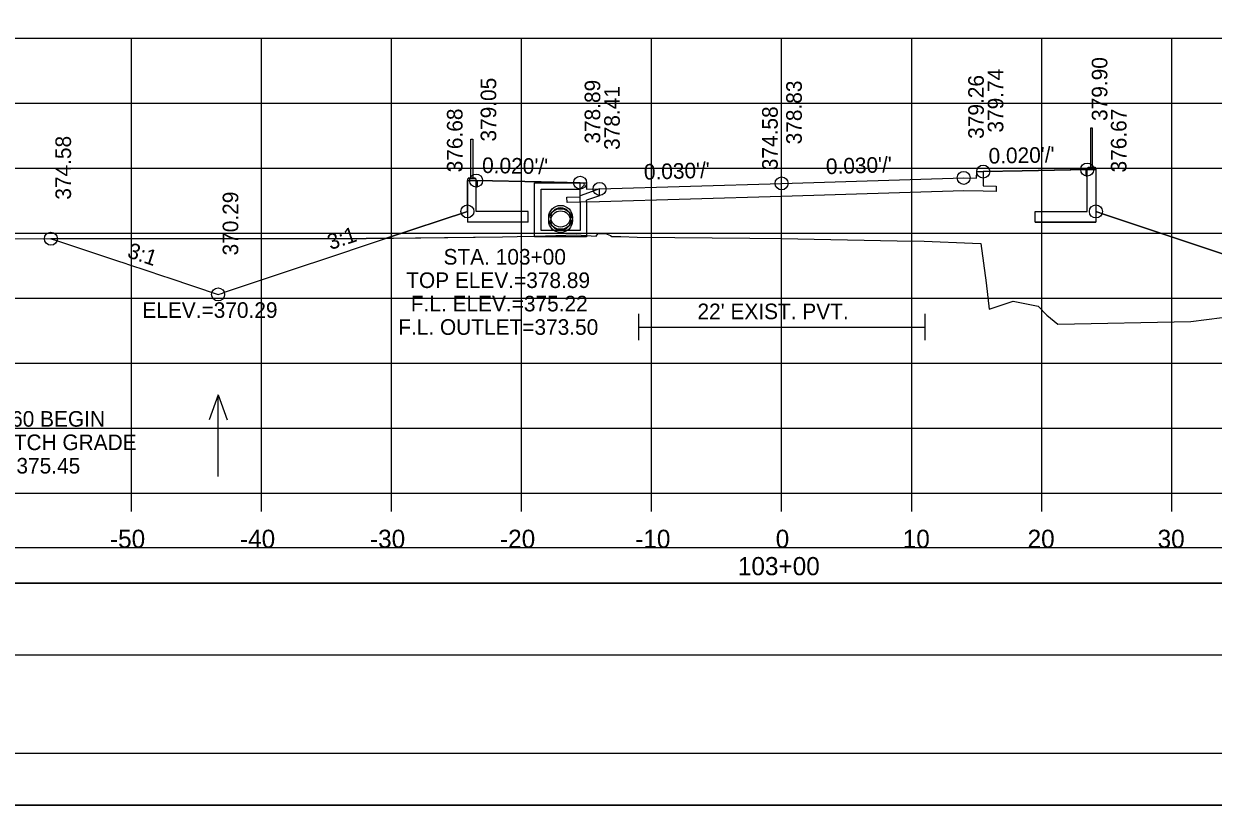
# Model space of a CAD drawing. Extents: x -37291014 to -37290680, y -936053 to -933067.
# Drawn here: x -37290901.4 to -37290809.9, y -935413.3 to -935353.2 of the extents above; entities that cross this region are included whole.
import ezdxf

# ---------------------------------------------------------------- set-up
doc = ezdxf.new("R2010")
doc.units = 0
for name, color, linetype in [('Default', 7, 'Continuous'), ('R_Alt Surface', 7, 'Continuous'), ('R_Axis', 7, 'Continuous'), ('R_Axis Annot', 7, 'Continuous'), ('R_Border', 7, 'Continuous'), ('R_Contours', 7, 'Continuous'), ('R_Exist Surface', 7, 'Continuous'), ('R_Fin Surface', 7, 'Continuous'), ('R_Grid', 7, 'Continuous'), ('R_No Plot', 7, 'Continuous'), ('R_Water', 7, 'Continuous'), ('R_Water Annot', 7, 'Continuous'), ('R_Xsect Elev', 7, 'Continuous'), ('R_Xsect Slope', 7, 'Continuous')]:
    doc.layers.add(name, color=color, linetype=linetype)

msp = doc.modelspace()

# ---------------------------------------------------------------- linework, layer by layer
at = {"layer": 'Default'}
for p, q in [((-37290819.352, -935361.226), (-37290819.352, -935364.226)), ((-37290819.185, -935361.226), (-37290819.352, -935361.226)), ((-37290819.185, -935364.226), (-37290819.185, -935361.226)), ((-37290867.018, -935365.076), (-37290867.018, -935362.076)), ((-37290867.018, -935362.076), (-37290866.852, -935362.076)), ((-37290866.852, -935362.076), (-37290866.852, -935365.076)), ((-37290819.602, -935364.309), (-37290819.539, -935364.246)), ((-37290819.602, -935367.64), (-37290819.602, -935364.309)), ((-37290819.539, -935364.226), (-37290818.997, -935364.226)), ((-37290819.539, -935364.246), (-37290819.539, -935364.226)), ((-37290819.539, -935364.246), (-37290818.997, -935364.246)), ((-37290818.997, -935364.226), (-37290818.997, -935364.246)), ((-37290818.997, -935364.246), (-37290818.935, -935364.309)), ((-37290818.935, -935364.309), (-37290818.935, -935368.473)), ((-37290867.206, -935365.097), (-37290867.268, -935365.16)), ((-37290867.268, -935365.16), (-37290867.268, -935368.463)), ((-37290866.664, -935365.076), (-37290867.206, -935365.076)), ((-37290867.206, -935365.076), (-37290867.206, -935365.097)), ((-37290866.664, -935365.097), (-37290867.206, -935365.097)), ((-37290866.664, -935365.097), (-37290866.664, -935365.076)), ((-37290866.602, -935365.16), (-37290866.664, -935365.097)), ((-37290866.602, -935367.63), (-37290866.602, -935365.16)), ((-37290862.598, -935367.63), (-37290866.602, -935367.63)), ((-37290862.598, -935368.463), (-37290862.598, -935367.63)), ((-37290823.605, -935368.473), (-37290823.605, -935367.64)), ((-37290823.605, -935367.64), (-37290819.602, -935367.64)), ((-37290862.598, -935368.463), (-37290867.268, -935368.463)), ((-37290823.605, -935368.473), (-37290818.935, -935368.473))]:
    msp.add_line(p, q, dxfattribs=at)
for points in [[(-37290819.685, -935364.913), (-37290819.602, -935364.913), (-37290819.602, -935364.413), (-37290819.685, -935364.413), (-37290819.685, -935364.913)], [(-37290866.518, -935365.764), (-37290866.602, -935365.764), (-37290866.602, -935365.264), (-37290866.518, -935365.264), (-37290866.518, -935365.764)]]:
    msp.add_lwpolyline(points, dxfattribs=at)
for points in [[(-37290992.481, -935396.216), (-37290693.722, -935396.216), (-37290693.722, -935393.51), (-37290992.481, -935393.51)], [(-37290992.481, -935401.738), (-37290693.722, -935401.738), (-37290693.722, -935396.216), (-37290992.481, -935396.216)]]:
    msp.add_lwpolyline(points, close=True, dxfattribs=at)
at = {"layer": 'R_Alt Surface'}
for points in [[(-37290827.602, -935364.573), (-37290827.602, -935365.666), (-37290826.592, -935365.686), (-37290826.602, -935366.103), (-37290827.602, -935366.083), (-37290829.102, -935366.053), (-37290843.102, -935366.478), (-37290857.102, -935366.904), (-37290858.602, -935366.934), (-37290859.602, -935366.954), (-37290859.612, -935366.537), (-37290858.602, -935366.517), (-37290858.602, -935365.424)], [(-37290854.102, -935375.522), (-37290854.102, -935377.522)], [(-37290832.102, -935375.522), (-37290832.102, -935377.522)], [(-37290854.102, -935376.522), (-37290832.102, -935376.522)]]:
    msp.add_lwpolyline(points, dxfattribs=at)
at = {"layer": 'R_Axis'}
for p, q in [((-37290993.102, -935389.31), (-37290693.102, -935389.31)), ((-37290893.102, -935390.71), (-37290893.102, -935389.31)), ((-37290883.102, -935390.71), (-37290883.102, -935389.31)), ((-37290873.102, -935390.71), (-37290873.102, -935389.31)), ((-37290863.102, -935390.71), (-37290863.102, -935389.31)), ((-37290853.102, -935390.71), (-37290853.102, -935389.31)), ((-37290843.102, -935390.71), (-37290843.102, -935389.31)), ((-37290833.102, -935390.71), (-37290833.102, -935389.31)), ((-37290823.102, -935390.71), (-37290823.102, -935389.31)), ((-37290813.102, -935390.71), (-37290813.102, -935389.31))]:
    msp.add_line(p, q, dxfattribs=at)
at = {"layer": 'R_Border'}
msp.add_line((-37290684.921, -935409.31), (-37291001.102, -935409.31), dxfattribs=at)
at = {"layer": 'R_Contours'}
for p, q in [((-37290819.602, -935367.64), (-37290819.602, -935364.913)), ((-37290823.605, -935368.473), (-37290823.605, -935367.64)), ((-37290823.605, -935367.64), (-37290819.602, -935367.64)), ((-37290818.935, -935367.64), (-37290818.935, -935368.473)), ((-37290818.935, -935368.473), (-37290823.605, -935368.473)), ((-37290875.057, -935369.719), (-37290899.307, -935369.733)), ((-37290873.484, -935369.7), (-37290875.057, -935369.719))]:
    msp.add_line(p, q, dxfattribs=at)
for points in [[(-37290819.685, -935364.415), (-37290824.602, -935364.513), (-37290827.602, -935364.573)], [(-37290819.602, -935364.913), (-37290819.685, -935364.913), (-37290819.685, -935364.415)], [(-37290858.602, -935365.424), (-37290861.602, -935365.364), (-37290866.602, -935365.264), (-37290867.272, -935365.264), (-37290867.273, -935367.63), (-37290873.484, -935369.7)], [(-37290827.602, -935364.573), (-37290827.602, -935365.666), (-37290826.592, -935365.686), (-37290826.602, -935366.103), (-37290827.602, -935366.083), (-37290829.102, -935366.053), (-37290843.102, -935366.478), (-37290857.102, -935366.904), (-37290858.602, -935366.934), (-37290859.602, -935366.954), (-37290859.612, -935366.537), (-37290858.602, -935366.517), (-37290858.602, -935365.424)], [(-37290818.931, -935367.64), (-37290818.935, -935367.64)], [(-37290796.525, -935375.107), (-37290798.192, -935374.566), (-37290798.385, -935374.504), (-37290818.199, -935367.884), (-37290818.931, -935367.64)], [(-37290899.307, -935369.733), (-37290899.032, -935369.823), (-37290894.19, -935371.43), (-37290893.608, -935371.621), (-37290893.34, -935371.711), (-37290891.917, -935372.183), (-37290890.728, -935372.583), (-37290890.247, -935372.746), (-37290886.444, -935374.02), (-37290886.119, -935373.911), (-37290885.943, -935373.853), (-37290879.345, -935371.649), (-37290879.077, -935371.559), (-37290873.484, -935369.7)], [(-37290873.484, -935369.7), (-37290864.579, -935369.594), (-37290863.438, -935369.567), (-37290862.072, -935369.536), (-37290858.894, -935369.432), (-37290857.375, -935369.542), (-37290857.24, -935369.359), (-37290856.642, -935369.332), (-37290856.266, -935369.487), (-37290856.162, -935369.56), (-37290855.462, -935369.571), (-37290854.208, -935369.605), (-37290845.556, -935369.695), (-37290843.14, -935369.726), (-37290834.226, -935369.884), (-37290832.13, -935369.923), (-37290828.416, -935370.082), (-37290827.782, -935370.106), (-37290827.37, -935373.135), (-37290827.148, -935375.144), (-37290825.302, -935374.524), (-37290823.371, -935374.908), (-37290822.714, -935375.622), (-37290821.871, -935376.316), (-37290811.629, -935376.105), (-37290809.219, -935375.784)]]:
    msp.add_lwpolyline(points, dxfattribs=at)
at = {"layer": 'R_Exist Surface'}
msp.add_lwpolyline([(-37290913.949, -935369.741), (-37290875.057, -935369.719), (-37290864.579, -935369.594), (-37290863.438, -935369.567), (-37290862.072, -935369.536), (-37290858.894, -935369.432), (-37290857.375, -935369.542), (-37290857.24, -935369.359), (-37290856.642, -935369.332), (-37290856.266, -935369.487), (-37290856.162, -935369.56), (-37290855.462, -935369.571), (-37290854.208, -935369.605), (-37290845.556, -935369.695), (-37290843.14, -935369.726), (-37290834.226, -935369.884), (-37290832.13, -935369.923), (-37290828.416, -935370.082), (-37290827.782, -935370.106), (-37290827.37, -935373.135), (-37290827.148, -935375.144), (-37290825.302, -935374.524), (-37290823.371, -935374.908), (-37290822.714, -935375.622), (-37290821.871, -935376.316), (-37290811.629, -935376.105), (-37290809.219, -935375.784)], dxfattribs=at)
at = {"layer": 'R_Fin Surface'}
msp.add_lwpolyline([(-37290899.307, -935369.733), (-37290899.032, -935369.823), (-37290894.19, -935371.43), (-37290893.608, -935371.621), (-37290893.34, -935371.711), (-37290891.917, -935372.183), (-37290890.728, -935372.583), (-37290890.247, -935372.746), (-37290886.444, -935374.02), (-37290886.119, -935373.911), (-37290885.943, -935373.853), (-37290879.345, -935371.649), (-37290879.077, -935371.559), (-37290873.484, -935369.7), (-37290867.273, -935367.63), (-37290867.272, -935365.264), (-37290866.602, -935365.264), (-37290861.602, -935365.364), (-37290858.602, -935365.424), (-37290858.102, -935365.424), (-37290858.101, -935365.924), (-37290857.102, -935365.904), (-37290843.102, -935365.478), (-37290829.102, -935365.053), (-37290828.103, -935365.073), (-37290828.102, -935364.573), (-37290827.602, -935364.573), (-37290824.602, -935364.513), (-37290819.602, -935364.413), (-37290818.932, -935364.413), (-37290818.931, -935367.64), (-37290818.199, -935367.884), (-37290798.385, -935374.504)], dxfattribs=at)
at = {"layer": 'R_Grid'}
for p, q in [((-37290993.102, -935354.31), (-37290693.102, -935354.31)), ((-37290893.102, -935389.31), (-37290893.102, -935354.31)), ((-37290883.102, -935389.31), (-37290883.102, -935354.31)), ((-37290873.102, -935389.31), (-37290873.102, -935354.31)), ((-37290863.102, -935389.31), (-37290863.102, -935354.31)), ((-37290853.102, -935389.31), (-37290853.102, -935354.31)), ((-37290843.102, -935389.31), (-37290843.102, -935354.31)), ((-37290833.102, -935389.31), (-37290833.102, -935354.31)), ((-37290823.102, -935389.31), (-37290823.102, -935354.31)), ((-37290813.102, -935389.31), (-37290813.102, -935354.31)), ((-37290993.102, -935359.31), (-37290693.102, -935359.31)), ((-37290993.102, -935364.31), (-37290693.102, -935364.31)), ((-37290993.102, -935369.31), (-37290693.102, -935369.31)), ((-37290993.102, -935374.31), (-37290693.102, -935374.31)), ((-37290993.102, -935379.31), (-37290693.102, -935379.31)), ((-37290993.102, -935384.31), (-37290693.102, -935384.31)), ((-37290993.102, -935389.31), (-37290693.102, -935389.31))]:
    msp.add_line(p, q, dxfattribs=at)
at = {"layer": 'R_No Plot'}
msp.add_line((-37291013.502, -935413.288), (-37290680.169, -935413.288), dxfattribs=at)
for points in [[(-37291013.509, -935199.955), (-37290680.169, -935199.955), (-37290680.169, -935413.293), (-37291013.509, -935413.293)], [(-37290767.182, -935203.85), (-37290747.562, -935203.85), (-37290747.562, -935213.73), (-37290731.449, -935213.73), (-37290708.25, -935213.73), (-37290708.25, -935238.062), (-37290684.921, -935238.062), (-37290684.921, -935409.31), (-37291001.102, -935409.31), (-37291001.102, -935203.85)]]:
    msp.add_lwpolyline(points, close=True, dxfattribs=at)
for centre, radius in [((-37290827.602, -935364.573), 0.5), ((-37290819.602, -935364.413), 0.5), ((-37290866.602, -935365.264), 0.5), ((-37290858.602, -935365.424), 0.5), ((-37290857.102, -935365.904), 0.5), ((-37290843.102, -935365.478), 0.5), ((-37290829.102, -935365.053), 0.5), ((-37290829.102, -935365.053), 0.5), ((-37290867.273, -935367.63), 0.5), ((-37290860.102, -935368.09), 0.917), ((-37290818.931, -935367.64), 0.5), ((-37290860.102, -935368.34), 0.917), ((-37290899.307, -935369.733), 0.5), ((-37290886.444, -935374.02), 0.5)]:
    msp.add_circle(centre, radius, dxfattribs=at)
at = {"layer": 'R_Water'}
for p, q in [((-37290862.102, -935365.424), (-37290858.352, -935365.424)), ((-37290861.602, -935365.924), (-37290858.602, -935365.924)), ((-37290858.269, -935365.589), (-37290858.602, -935365.924)), ((-37290857.102, -935365.904), (-37290858.602, -935366.424)), ((-37290858.269, -935365.589), (-37290858.352, -935365.424)), ((-37290858.602, -935366.924), (-37290858.602, -935366.424)), ((-37290857.102, -935366.433), (-37290858.102, -935366.78)), ((-37290858.102, -935366.924), (-37290858.102, -935366.78))]:
    msp.add_line(p, q, dxfattribs=at)
for points in [[(-37290858.102, -935366.924), (-37290858.102, -935369.59), (-37290860.102, -935369.59), (-37290862.102, -935369.59), (-37290862.102, -935365.424)], [(-37290858.602, -935366.924), (-37290858.602, -935369.09), (-37290860.102, -935369.09), (-37290861.602, -935369.09), (-37290861.602, -935365.924)], [(-37290857.102, -935366.433), (-37290857.102, -935365.904)]]:
    msp.add_lwpolyline(points, dxfattribs=at)
for centre in [(-37290860.102, -935368.09), (-37290860.102, -935368.34)]:
    msp.add_circle(centre, 0.75, dxfattribs=at)
at = {"layer": 'R_Water Annot'}
for p, q in [((-37290886.444, -935381.741), (-37290887.144, -935383.664)), ((-37290886.444, -935388.025), (-37290886.444, -935381.741)), ((-37290886.444, -935381.741), (-37290885.744, -935383.664))]:
    msp.add_line(p, q, dxfattribs=at)
at = {"layer": 'R_Xsect Elev'}
msp.add_line((-37290843.102, -935369.727), (-37290843.102, -935357.464), dxfattribs=at)

# ---------------------------------------------------------------- texts
at = {"layer": 'R_Axis Annot'}
for s, p in [('-50', (-37290894.761, -935393.51)), ('-40', (-37290884.761, -935393.51)), ('-30', (-37290874.761, -935393.51)), ('-20', (-37290864.761, -935393.51)), ('-10', (-37290854.364, -935393.51)), ('0', (-37290843.559, -935393.51)), ('10', (-37290833.791, -935393.51)), ('20', (-37290824.187, -935393.51)), ('30', (-37290814.187, -935393.51)), ('103+00', (-37290846.469, -935395.61))]:
    msp.add_text(s, height=1.4, dxfattribs=at).set_placement(p)
at = {"layer": 'R_Water'}
msp.add_text("22' EXIST. PVT.", height=1.2, dxfattribs=at).set_placement((-37290849.575, -935375.922))
at = {"layer": 'R_Water Annot'}
for s, p in [('STA. 103+00', (-37290869.105, -935371.724)), ('TOP ELEV.=378.89', (-37290871.977, -935373.524)), ('F.L. ELEV.=375.22', (-37290871.623, -935375.324)), ('F.L. OUTLET=373.50', (-37290872.592, -935377.124))]:
    msp.add_text(s, height=1.2, dxfattribs=at).set_placement(p)
at = {"layer": 'R_Xsect Elev'}
for s, p in [('379.90', (-37290818.052, -935360.678)), ('379.74', (-37290826.052, -935361.573)), ('379.05', (-37290865.052, -935362.264)), ('378.89', (-37290857.052, -935362.424)), ('378.41', (-37290855.552, -935362.904)), ('378.83', (-37290841.552, -935362.478)), ('379.26', (-37290827.552, -935362.053)), ('379.26', (-37290827.552, -935362.053)), ('376.68', (-37290867.646, -935364.63)), ('374.58', (-37290843.402, -935364.464)), ('376.67', (-37290816.578, -935364.64)), ('374.58', (-37290897.757, -935366.733)), ('370.29', (-37290884.894, -935371.02))]:
    msp.add_text(s, height=1.2, rotation=90, dxfattribs=at).set_placement(p)
for s, p in [('ELEV.=370.29', (-37290892.27, -935375.82)), ('STA. 102+60 BEGIN ', (-37290909.993, -935384.188)), ('-12.90% LT. DITCH GRADE', (-37290912.955, -935385.988)), ('ELEV. = 375.45', (-37290908.335, -935387.788))]:
    msp.add_text(s, height=1.2, dxfattribs=at).set_placement(p)
at = {"layer": 'R_Xsect Slope'}
for s, rotation, p in [("0.020'/'", 1.14576, (-37290827.175, -935363.964)), ("0.020'/'", 358.85424, (-37290866.151, -935364.673)), ("0.030'/'", 1.74038, (-37290839.68, -935364.774)), ("0.030'/'", 1.74038, (-37290853.68, -935365.2)), ('3:1', 18.43323, (-37290877.805, -935370.613)), ('3:1', 341.56677, (-37290893.506, -935371.139))]:
    msp.add_text(s, height=1.2, rotation=rotation, dxfattribs=at).set_placement(p)

doc.saveas('drawing.dxf')
